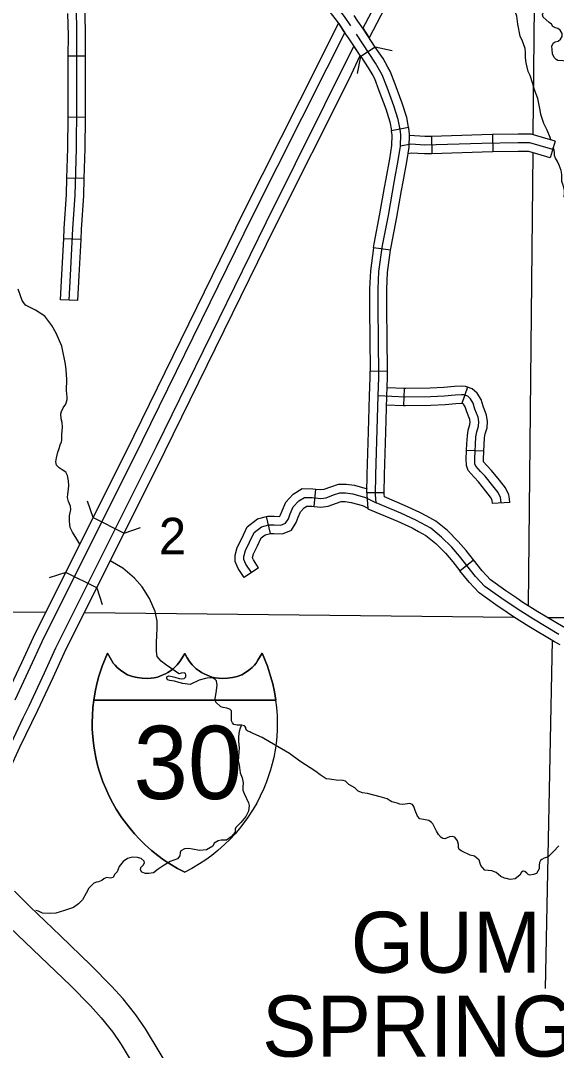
# Model space of a CAD drawing. Extents: x 813775 to 1157140, y 1757555 to 1979907.
# Drawn here: x 966252 to 975531, y 1804482 to 1822306 of the extents above; entities that cross this region are included whole.
import ezdxf

# ---------------------------------------------------------------- set-up
doc = ezdxf.new("R2010")
doc.units = 0
for name, color, linetype in [('Level 10', 7, 'Continuous'), ('Level 19', 7, 'Continuous'), ('Level 23', 7, 'Continuous'), ('Level 31', 7, 'Continuous'), ('Level 32', 7, 'Continuous'), ('Level 35', 7, 'Continuous'), ('Level 37', 7, 'Continuous'), ('Level 38', 7, 'Continuous'), ('Level 39', 7, 'Continuous'), ('Level 4', 7, 'Continuous'), ('Level 5', 7, 'Continuous'), ('Level 6', 7, 'Continuous')]:
    doc.layers.add(name, color=color, linetype=linetype)

msp = doc.modelspace()

# ---------------------------------------------------------------- linework, layer by layer
at = {"layer": 'Level 10'}
for points in [[(966942, 1806463), (966410, 1806971), (966147, 1807238)], [(965792, 1806887), (966060, 1806615), (966596, 1806102)], [(971631, 1799923), (971368, 1800176), (971185, 1800370), (971078, 1800491), (970877, 1800737), (970608, 1801152), (970151, 1801951), (969695, 1802707), (968904, 1804044), (968417, 1804857), (968250, 1805099), (968026, 1805372), (967828, 1805595), (967470, 1805960), (966941, 1806464)], [(966597, 1806101), (967119, 1805604), (967462, 1805254), (967645, 1805048), (967850, 1804798), (967996, 1804586), (968475, 1803788), (969266, 1802450), (969720, 1801698), (970181, 1800892), (970472, 1800442), (970697, 1800168), (970815, 1800033), (971013, 1799824), (971284, 1799563)]]:
    msp.add_lwpolyline(points, dxfattribs=at)
at = {"layer": 'Level 19'}
for p, q in [((972024, 1821867), (970500, 1818807)), ((972134, 1821700), (972024, 1821867)), ((971944, 1821292), (972134, 1821700)), ((970652, 1818730), (971944, 1821292)), ((970500, 1818807), (968598, 1814926)), ((968751, 1814850), (970652, 1818730)), ((968598, 1814926), (966859, 1811443)), ((967011, 1811367), (968751, 1814850))]:
    msp.add_line(p, q, dxfattribs=at)
for points in [[(972227, 1822257), (972339, 1822476), (972780, 1823310), (972987, 1823686), (973351, 1824331)], [(973499, 1824247), (973135, 1823603), (972930, 1823229), (972490, 1822397), (972289, 1822009)], [(971408, 1821562), (971759, 1822261)], [(971759, 1822261), (971867, 1822097)], [(972289, 1822009), (972191, 1822158), (972181, 1822171), (972227, 1822257)], [(971560, 1821486), (971867, 1822097)], [(972182, 1822171), (972289, 1822009)], [(970116, 1819000), (971408, 1821562)], [(970268, 1818924), (971560, 1821486)], [(968213, 1815116), (970116, 1819000)], [(968365, 1815041), (970268, 1818924)], [(966474, 1811634), (968213, 1815116)], [(966626, 1811559), (968365, 1815041)], [(966005, 1810621), (966273, 1811197), (966474, 1811634)], [(966160, 1810550), (966426, 1811123), (966626, 1811559)], [(966859, 1811443), (966661, 1811011), (966395, 1810440)], [(966549, 1810368), (966814, 1810937), (967011, 1811367)], [(966395, 1810440), (966292, 1810231), (966087, 1809802), (965904, 1809413)], [(966058, 1809340), (966241, 1809729), (966446, 1810159), (966549, 1810368)]]:
    msp.add_lwpolyline(points, dxfattribs=at)
at = {"layer": 'Level 23'}
msp.add_line((970670, 1810545), (970668, 1810545), dxfattribs=at)
for points in [[(967519, 1810545), (967541, 1810690), (967570, 1810828), (967608, 1810961), (967662, 1811132), (967755, 1811355), (967826, 1811237), (967857, 1811187), (967888, 1811148), (967927, 1811110), (967984, 1811062), (968042, 1811021), (968106, 1810985), (968188, 1810954), (968269, 1810934), (968355, 1810922), (968446, 1810920), (968512, 1810925), (968566, 1810931), (968625, 1810944), (968706, 1810974), (968759, 1810997), (968803, 1811020), (968846, 1811049), (968897, 1811089), (968965, 1811155), (969012, 1811212), (969051, 1811276), (969094, 1811351)], [(969094, 1811351), (969051, 1811276), (969012, 1811212), (968965, 1811155), (968897, 1811089), (968846, 1811049), (968803, 1811020), (968759, 1810997), (968706, 1810974), (968625, 1810944), (968566, 1810931), (968512, 1810925), (968446, 1810920), (968355, 1810922), (968269, 1810934), (968188, 1810954), (968106, 1810985), (968042, 1811021), (967984, 1811062), (967927, 1811110), (967888, 1811148), (967857, 1811187), (967826, 1811237), (967755, 1811355), (967662, 1811132), (967608, 1810961), (967570, 1810828), (967541, 1810690), (967519, 1810545)], [(969094, 1811351), (969138, 1811276), (969177, 1811212), (969224, 1811155), (969292, 1811089), (969343, 1811049), (969386, 1811020), (969430, 1810997), (969483, 1810974), (969564, 1810944), (969623, 1810931), (969677, 1810925), (969743, 1810920), (969834, 1810922), (969920, 1810934), (970001, 1810954), (970083, 1810985), (970147, 1811021), (970205, 1811062), (970262, 1811110), (970301, 1811148), (970332, 1811187), (970363, 1811237), (970434, 1811355), (970527, 1811132), (970581, 1810961), (970618, 1810828), (970648, 1810690), (970670, 1810545)], [(970670, 1810545), (970648, 1810690), (970618, 1810828), (970581, 1810961), (970527, 1811132), (970434, 1811355), (970363, 1811237), (970332, 1811187), (970301, 1811148), (970262, 1811110), (970205, 1811062), (970147, 1811021), (970083, 1810985), (970001, 1810954), (969920, 1810934), (969834, 1810922), (969743, 1810920), (969677, 1810925), (969623, 1810931), (969564, 1810944), (969483, 1810974), (969430, 1810997), (969386, 1811020), (969343, 1811049), (969292, 1811089), (969224, 1811155), (969177, 1811212), (969138, 1811276), (969094, 1811351)], [(967521, 1810545), (967506, 1810415), (967496, 1810281), (967493, 1810156), (967494, 1810043), (967501, 1809911), (967513, 1809797), (967524, 1809714), (967554, 1809554), (967580, 1809442), (967608, 1809340), (967642, 1809234), (967679, 1809129), (967726, 1809014), (967786, 1808883), (967848, 1808764), (967910, 1808657), (968006, 1808509), (968124, 1808350), (968223, 1808232), (968310, 1808139), (968405, 1808045), (968520, 1807943), (968627, 1807857), (968728, 1807783), (968838, 1807710), (968969, 1807631), (969094, 1807565)], [(969094, 1807565), (968969, 1807631), (968838, 1807710), (968728, 1807783), (968627, 1807857), (968520, 1807943), (968405, 1808045), (968310, 1808139), (968223, 1808232), (968124, 1808350), (968006, 1808509), (967910, 1808657), (967848, 1808764), (967786, 1808883), (967726, 1809014), (967679, 1809129), (967642, 1809234), (967608, 1809340), (967580, 1809442), (967554, 1809554), (967524, 1809714), (967513, 1809797), (967501, 1809911), (967494, 1810043), (967493, 1810156), (967496, 1810281), (967506, 1810415), (967521, 1810545)], [(970670, 1810545), (967519, 1810545)], [(967519, 1810545), (970670, 1810545)], [(967519, 1810545), (970670, 1810545)], [(970668, 1810545), (970683, 1810415), (970693, 1810281), (970696, 1810156), (970695, 1810043), (970688, 1809911), (970676, 1809797), (970664, 1809714), (970635, 1809554), (970609, 1809442), (970581, 1809340), (970547, 1809234), (970510, 1809129), (970463, 1809014), (970403, 1808883), (970341, 1808764), (970279, 1808657), (970183, 1808509), (970065, 1808350), (969966, 1808232), (969879, 1808139), (969784, 1808045), (969669, 1807943), (969562, 1807857), (969461, 1807783), (969351, 1807710), (969220, 1807631), (969094, 1807565)], [(970668, 1810545), (970683, 1810415), (970693, 1810281), (970696, 1810156), (970695, 1810043), (970688, 1809911), (970676, 1809797), (970664, 1809714), (970635, 1809554), (970609, 1809442), (970581, 1809340), (970547, 1809234), (970510, 1809129), (970463, 1809014), (970403, 1808883), (970341, 1808764), (970279, 1808657), (970183, 1808509), (970065, 1808350), (969966, 1808232), (969879, 1808139), (969784, 1808045), (969669, 1807943), (969562, 1807857), (969461, 1807783), (969351, 1807710), (969220, 1807631), (969094, 1807565)]]:
    msp.add_lwpolyline(points, dxfattribs=at)
at = {"layer": 'Level 31'}
for p, q in [((972675, 1820405), (972970, 1820461)), ((972660, 1818331), (972363, 1818371)), ((972304, 1816241), (972604, 1816244)), ((972550, 1814130), (972250, 1814133)), ((972250, 1814133), (972250, 1814133)), ((973860, 1812785), (974095, 1812972))]:
    msp.add_line(p, q, dxfattribs=at)
for points in [[(971969, 1822214), (971862, 1822379), (971680, 1822607), (971433, 1822977), (971177, 1823305), (970999, 1823522), (970717, 1823840), (970626, 1823916), (970516, 1824001), (970390, 1824095), (970292, 1824140), (970117, 1824205), (970033, 1824267), (969945, 1824345), (969890, 1824478), (969864, 1824631), (969864, 1824972), (969874, 1825319), (969871, 1825736), (969874, 1825837), (969884, 1826032), (969893, 1826574), (969910, 1827828), (969914, 1828922)], [(967119, 1817903), (967158, 1818701), (967197, 1819287), (967219, 1820095), (967226, 1820830), (967229, 1822048), (967219, 1822577)], [(971778, 1822232), (971740, 1822292), (971538, 1822549)], [(972395, 1821849), (972191, 1822158), (972093, 1822297), (972030, 1822395)], [(972144, 1821684), (971943, 1821989), (971844, 1822130), (971778, 1822232)], [(972409, 1813960), (972400, 1814105), (972403, 1814446), (972443, 1815809), (972455, 1816129), (972449, 1816817), (972445, 1817301), (972445, 1817662), (972458, 1817961), (972520, 1818416), (972621, 1818932), (972728, 1819540), (972793, 1819887), (972831, 1820131), (972836, 1820334), (972825, 1820420), (972793, 1820592), (972718, 1820829), (972598, 1821151), (972514, 1821369), (972400, 1821569), (972067, 1822074)], [(972610, 1821502), (972528, 1821648), (972395, 1821849), (972144, 1821684)], [(972144, 1821684), (972272, 1821491), (972349, 1821354)], [(972970, 1820461), (972938, 1820628), (972860, 1820877), (972738, 1821205), (972650, 1821433), (972610, 1821502)], [(972349, 1821354), (972378, 1821304), (972458, 1821098), (972576, 1820780), (972647, 1820555), (972675, 1820405)], [(972849, 1819363), (972875, 1819513), (972940, 1819861), (972981, 1820117), (972986, 1820342), (972973, 1820443), (972970, 1820461)], [(972553, 1819415), (972580, 1819566), (972645, 1819913), (972682, 1820144), (972686, 1820326), (972677, 1820396), (972675, 1820405)], [(972363, 1818371), (972372, 1818440), (972473, 1818959), (972553, 1819415)], [(972660, 1818331), (972668, 1818391), (972768, 1818904), (972849, 1819363)], [(972363, 1818371), (972309, 1817974), (972295, 1817666), (972295, 1817300), (972296, 1817297)], [(972595, 1817300), (972595, 1817302), (972595, 1817659), (972608, 1817948), (972660, 1818331)], [(967096, 1817468), (967119, 1817903)], [(972296, 1817298), (972299, 1816816), (972304, 1816241)], [(972604, 1816244), (972599, 1816818), (972595, 1817300)], [(972275, 1815191), (972293, 1815814), (972305, 1816131), (972304, 1816241)], [(972575, 1815183), (972593, 1815804), (972605, 1816127), (972604, 1816244)], [(972250, 1814133), (972253, 1814449), (972275, 1815191)], [(972550, 1814130), (972553, 1814443), (972575, 1815183)], [(972250, 1814133), (972250, 1814101), (972265, 1813858), (972776, 1813641), (973030, 1813524), (973143, 1813463)], [(973285, 1813727), (973164, 1813793), (972898, 1813916), (972553, 1814062), (972550, 1814109), (972550, 1814130)], [(975572, 1811682), (975133, 1811946), (974867, 1812112), (974569, 1812316), (974293, 1812514), (974131, 1812686), (973852, 1813037), (973720, 1813191), (973541, 1813366), (973356, 1813519), (973097, 1813658), (972837, 1813779), (972409, 1813960)], [(974095, 1812972), (973968, 1813133), (973829, 1813293), (973642, 1813478), (973440, 1813644), (973285, 1813727)], [(973143, 1813463), (973272, 1813394), (973441, 1813255), (973610, 1813088), (973736, 1812941), (973860, 1812785)], [(974847, 1812308), (974655, 1812439), (974392, 1812628), (974244, 1812785), (974095, 1812972)], [(974677, 1812060), (974483, 1812193), (974194, 1812401), (974017, 1812588), (973860, 1812785)], [(975731, 1811770), (975645, 1811814), (975211, 1812074), (974949, 1812237), (974847, 1812308)], [(975597, 1811502), (975500, 1811551), (975055, 1811818), (974785, 1811986), (974677, 1812060)]]:
    msp.add_lwpolyline(points, dxfattribs=at)
at = {"layer": 'Level 32'}
for p, q in [((967378, 1821688), (967078, 1821689)), ((967374, 1820631), (967074, 1820634)), ((973366, 1820302), (973376, 1820003)), ((974425, 1820333), (974428, 1820033)), ((975510, 1820218), (975424, 1819930)), ((967355, 1819572), (967055, 1819581)), ((967299, 1818515), (966999, 1818529)), ((967246, 1817460), (966946, 1817475)), ((973991, 1815964), (973894, 1815680)), ((972896, 1815939), (972883, 1815639)), ((974274, 1814854), (973974, 1814863)), ((971337, 1813897), (971364, 1814196)), ((974722, 1813966), (974422, 1813948)), ((970580, 1813429), (970509, 1813721)), ((970374, 1812836), (970125, 1812669))]:
    msp.add_line(p, q, dxfattribs=at)
for points in [[(967078, 1821689), (967079, 1822047), (967072, 1822427)], [(967378, 1821688), (967379, 1822049), (967372, 1822435)], [(967074, 1820634), (967076, 1820831), (967078, 1821689)], [(967374, 1820631), (967376, 1820830), (967378, 1821688)], [(967055, 1819581), (967069, 1820098), (967074, 1820634)], [(967355, 1819572), (967369, 1820093), (967374, 1820631)], [(973366, 1820302), (973254, 1820299), (972986, 1820317)], [(974425, 1820333), (974237, 1820331), (973366, 1820302)], [(975510, 1820218), (975291, 1820283), (975091, 1820338), (974869, 1820338), (974425, 1820333)], [(975467, 1820074), (975249, 1820139), (975071, 1820188), (974870, 1820188), (974241, 1820181), (973251, 1820149), (973008, 1820165), (972831, 1820131)], [(973376, 1820003), (973249, 1819998), (973017, 1820014), (972963, 1820003)], [(974428, 1820033), (974244, 1820031), (973376, 1820003)], [(975424, 1819930), (975208, 1819995), (975051, 1820038), (974871, 1820038), (974428, 1820033)], [(966999, 1818529), (967008, 1818710), (967047, 1819294), (967055, 1819581)], [(967299, 1818515), (967307, 1818693), (967346, 1819280), (967355, 1819572)], [(966946, 1817475), (966969, 1817910), (966999, 1818529)], [(967246, 1817460), (967268, 1817895), (967299, 1818515)], [(973991, 1815964), (973959, 1815975), (973887, 1815980), (973768, 1815974), (973582, 1815955), (973345, 1815944), (972921, 1815938), (972896, 1815939)], [(974274, 1814854), (974277, 1814962), (974287, 1815084), (974298, 1815153), (974330, 1815260), (974337, 1815370), (974321, 1815479), (974262, 1815633), (974225, 1815746), (974160, 1815855), (974074, 1815935), (973991, 1815964)], [(974572, 1813957), (974569, 1814010), (974562, 1814051), (974520, 1814137), (974428, 1814256), (974295, 1814419), (974216, 1814503), (974135, 1814594), (974120, 1814636), (974117, 1814719), (974123, 1814852), (974127, 1814971), (974138, 1815102), (974151, 1815187), (974182, 1815287), (974187, 1815364), (974175, 1815440), (974120, 1815583), (974088, 1815684), (974042, 1815760), (973995, 1815804), (973929, 1815826), (973885, 1815830), (973780, 1815825), (973593, 1815805), (973350, 1815794), (972918, 1815787), (972443, 1815809)], [(972896, 1815939), (972599, 1815952)], [(972883, 1815639), (972589, 1815652)], [(973899, 1815678), (973883, 1815679), (973791, 1815675), (973604, 1815656), (973354, 1815644), (972916, 1815637), (972883, 1815639)], [(973974, 1814863), (973977, 1814979), (973989, 1815120), (974004, 1815220), (974033, 1815315), (974036, 1815357), (974029, 1815402), (973979, 1815533), (973950, 1815621), (973924, 1815665), (973917, 1815672), (973894, 1815680)], [(974422, 1813948), (974420, 1813994), (974418, 1814005), (974392, 1814057), (974310, 1814162), (974182, 1814321), (974105, 1814402), (974003, 1814517), (973971, 1814608), (973967, 1814720), (973974, 1814858), (973974, 1814863)], [(974722, 1813966), (974718, 1814027), (974707, 1814097), (974648, 1814217), (974545, 1814349), (974408, 1814518), (974326, 1814605), (974269, 1814669), (974267, 1814718), (974273, 1814847), (974274, 1814854)], [(970509, 1813721), (970533, 1813726), (970643, 1813726), (970730, 1813724), (970742, 1813729), (970755, 1813750), (970780, 1813822), (970845, 1813971), (970974, 1814109), (971129, 1814205), (971312, 1814200), (971364, 1814196)], [(971364, 1814196), (971448, 1814188), (971508, 1814194), (971623, 1814237), (971756, 1814282), (971890, 1814282), (972037, 1814263), (972251, 1814202)], [(970551, 1813576), (970641, 1813576), (970758, 1813573), (970842, 1813609), (970891, 1813683), (970920, 1813768), (970972, 1813888), (971070, 1813992), (971170, 1814054), (971303, 1814050), (971449, 1814037), (971543, 1814047), (971673, 1814096), (971780, 1814132), (971880, 1814132), (972007, 1814115), (972224, 1814054), (972409, 1813960)], [(970569, 1813426), (970639, 1813426), (970787, 1813422), (970943, 1813489), (971027, 1813617), (971060, 1813714), (971100, 1813805), (971165, 1813875), (971211, 1813903), (971295, 1813901), (971337, 1813897)], [(971337, 1813897), (971450, 1813887), (971578, 1813900), (971723, 1813954), (971804, 1813982), (971871, 1813982), (971977, 1813968), (972170, 1813913), (972265, 1813865)], [(970125, 1812669), (970021, 1812825), (969967, 1812944), (969967, 1813053), (970005, 1813187), (970082, 1813343), (970174, 1813544), (970355, 1813683), (970509, 1813721)], [(970249, 1812753), (970152, 1812899), (970117, 1812977), (970117, 1813032), (970146, 1813133), (970217, 1813279), (970295, 1813447), (970421, 1813545), (970551, 1813576)], [(970374, 1812836), (970284, 1812972), (970267, 1813009), (970267, 1813011), (970286, 1813078), (970353, 1813214), (970416, 1813351), (970488, 1813407), (970580, 1813429)]]:
    msp.add_lwpolyline(points, dxfattribs=at)
at = {"layer": 'Level 35'}
for points in [[(975407, 1822276), (975353, 1822318), (975301, 1822366), (975290, 1822407), (975289, 1822415), (975324, 1822484), (975389, 1822540), (975446, 1822574), (975461, 1822607), (975460, 1822645), (975429, 1822710)], [(975009, 1821575), (974993, 1821660), (974998, 1821752), (974991, 1821826), (974965, 1821887), (974941, 1821951), (974903, 1822035), (974862, 1822246), (974847, 1822381), (974806, 1822492)], [(975737, 1821606), (975686, 1821605), (975645, 1821609), (975558, 1821616), (975524, 1821631), (975490, 1821665), (975465, 1821733), (975459, 1821804), (975449, 1821865), (975472, 1821914), (975510, 1821941), (975561, 1821953), (975604, 1821987), (975630, 1822031), (975631, 1822081), (975593, 1822140), (975557, 1822171), (975516, 1822183), (975468, 1822206), (975448, 1822243), (975407, 1822276)], [(975267, 1820666), (975233, 1820843), (975211, 1820960), (975149, 1821106), (975123, 1821211), (975076, 1821355), (975044, 1821426), (975009, 1821575)], [(975433, 1820240), (975422, 1820282), (975369, 1820408), (975315, 1820526), (975267, 1820666)], [(975494, 1820062), (975477, 1820107)], [(975663, 1819248), (975672, 1819312), (975668, 1819366), (975648, 1819460), (975626, 1819524), (975623, 1819591), (975624, 1819640), (975612, 1819713), (975576, 1819803), (975548, 1819870), (975516, 1819928), (975495, 1819973), (975497, 1820021), (975494, 1820062)], [(966335, 1817380), (966277, 1817459), (966210, 1817659)], [(967029, 1816361), (966964, 1816674), (966868, 1816899), (966794, 1817030), (966673, 1817193), (966508, 1817294), (966428, 1817334), (966335, 1817380)], [(967057, 1815789), (967050, 1815904), (967052, 1816093), (967041, 1816263), (967029, 1816361)], [(966964, 1815043), (966964, 1815145), (966977, 1815268), (966974, 1815348), (966956, 1815413), (966950, 1815501), (966958, 1815542), (966989, 1815601), (967038, 1815665), (967057, 1815749), (967057, 1815789)], [(966970, 1815103), (966970, 1815104)], [(966973, 1814533), (966918, 1814567), (966874, 1814611), (966864, 1814671), (966873, 1814741), (966898, 1814834), (966920, 1814898), (966940, 1814965), (966961, 1815014), (966964, 1815043)], [(967084, 1813981), (967065, 1814052), (967072, 1814108), (967082, 1814194), (967089, 1814261), (967084, 1814338), (967074, 1814371), (967062, 1814432), (967037, 1814489), (966973, 1814533)], [(967278, 1813245), (967224, 1813332), (967149, 1813454), (967109, 1813534), (967107, 1813585), (967101, 1813643), (967097, 1813735), (967121, 1813844), (967116, 1813902), (967084, 1813981)], [(968617, 1811913), (968583, 1812076), (968484, 1812305), (968359, 1812507), (968227, 1812653), (968020, 1812826), (967805, 1812958)], [(968686, 1811217), (968617, 1811302), (968606, 1811387), (968606, 1811536), (968609, 1811671), (968620, 1811783), (968617, 1811913)], [(968929, 1811044), (968856, 1811097), (968761, 1811163), (968686, 1811217)], [(968923, 1810943), (968997, 1810920), (969042, 1810916), (969082, 1810917), (969114, 1810950), (969114, 1810981), (969107, 1811003), (969082, 1811019), (969033, 1811012), (968998, 1810999), (968969, 1811015), (968929, 1811044)], [(969638, 1810669), (969657, 1810805), (969644, 1810876), (969613, 1810906), (969576, 1810932), (969478, 1810924), (969342, 1810890), (969188, 1810815), (969055, 1810834), (969024, 1810844), (968994, 1810847), (968915, 1810871), (968835, 1810882), (968798, 1810898), (968784, 1810924), (968787, 1810948), (968822, 1810967), (968875, 1810953), (968923, 1810943)], [(969902, 1810357), (969882, 1810380), (969857, 1810395), (969823, 1810406), (969761, 1810418), (969719, 1810429), (969631, 1810508), (969619, 1810572), (969638, 1810669)], [(970223, 1809993), (970189, 1810005), (970171, 1810023), (970155, 1810050), (970152, 1810069), (970128, 1810098), (970079, 1810113), (970004, 1810111), (969947, 1810121), (969921, 1810152), (969905, 1810186), (969902, 1810357)], [(970079, 1810113), (970057, 1810057), (970035, 1810000), (970024, 1809913), (970024, 1809828), (970038, 1809717), (970033, 1809649), (970024, 1809559), (970022, 1809496), (970038, 1809426), (970057, 1809287), (970087, 1809197), (970106, 1809115), (970098, 1809039)], [(971439, 1809252), (971363, 1809308), (971087, 1809490), (970906, 1809618), (970662, 1809767), (970433, 1809900), (970239, 1809985), (970223, 1809993)], [(973677, 1808177), (973598, 1808144), (973563, 1808147), (973537, 1808165), (973489, 1808216), (973457, 1808277), (973391, 1808402), (973367, 1808428), (973324, 1808460), (973229, 1808476), (973168, 1808492), (973123, 1808535), (973085, 1808636), (973061, 1808702), (973040, 1808739), (972992, 1808755), (972873, 1808737), (972820, 1808742), (972772, 1808760), (972679, 1808787), (972650, 1808803), (972599, 1808835), (972557, 1808848), (972477, 1808870), (972262, 1808931), (972174, 1808939), (972100, 1808971), (972039, 1809024), (971938, 1809082), (971877, 1809141), (971840, 1809154), (971718, 1809159), (971603, 1809175), (971542, 1809183), (971439, 1809252)], [(970098, 1809039), (970101, 1808989), (970125, 1808929), (970198, 1808768), (970212, 1808719), (970201, 1808624), (970152, 1808529), (970068, 1808425), (969978, 1808338), (969967, 1808311), (969965, 1808257), (969899, 1808178), (969820, 1808121), (969723, 1808118), (969671, 1808107), (969603, 1808066), (969581, 1808015), (969472, 1807955), (969350, 1807941), (969228, 1807966), (969168, 1807976), (969092, 1807968), (969029, 1807938), (969016, 1807906), (969008, 1807851), (968967, 1807797)], [(973891, 1807929), (973849, 1807962), (973836, 1807996), (973836, 1808044), (973820, 1808108), (973770, 1808172), (973733, 1808186), (973677, 1808177)], [(975570, 1808020), (975482, 1807927), (975389, 1807834), (975320, 1807810), (975280, 1807789), (975254, 1807770), (975235, 1807736), (975233, 1807680), (975230, 1807622), (975188, 1807544), (975134, 1807528), (975068, 1807515), (975041, 1807526), (975018, 1807550), (974986, 1807576), (974954, 1807584), (974927, 1807566), (974895, 1807515), (974818, 1807454), (974728, 1807438), (974667, 1807459), (974632, 1807462), (974566, 1807494), (974489, 1807560)], [(968967, 1807797), (968842, 1807749), (968723, 1807676), (968633, 1807619), (968552, 1807556), (968475, 1807542), (968413, 1807542), (968350, 1807567), (968331, 1807605), (968337, 1807646), (968372, 1807687), (968397, 1807728), (968391, 1807760), (968342, 1807806), (968274, 1807823), (968187, 1807828), (968106, 1807806), (968027, 1807752), (967959, 1807665), (967923, 1807572), (967880, 1807529), (967853, 1807474), (967807, 1807464), (967741, 1807472), (967695, 1807453), (967657, 1807420), (967600, 1807398), (967565, 1807395), (967521, 1807376)], [(974223, 1807682), (974192, 1807773), (974152, 1807808), (974110, 1807842), (974038, 1807863), (973891, 1807929)], [(974489, 1807560), (974415, 1807590), (974351, 1807595), (974293, 1807603), (974248, 1807648), (974223, 1807682)], [(967521, 1807376), (967432, 1807290), (967389, 1807206), (967326, 1807089), (967253, 1807021), (967166, 1806953), (967013, 1806904), (966861, 1806858), (966747, 1806852), (966633, 1806858), (966565, 1806890), (966519, 1806906)]]:
    msp.add_lwpolyline(points, dxfattribs=at)
at = {"layer": 'Level 38'}
for points in [[(972395, 1821850), (972689, 1821790)], [(972084, 1821391), (972144, 1821684)]]:
    msp.add_lwpolyline(points, dxfattribs=at)
at = {"layer": 'Level 39'}
for p, q in [((967507, 1813703), (967412, 1813988)), ((967507, 1813703), (968043, 1813435)), ((968043, 1813435), (968328, 1813530)), ((967033, 1812755), (966748, 1812660)), ((967570, 1812487), (967033, 1812755)), ((967570, 1812487), (967665, 1812202))]:
    msp.add_line(p, q, dxfattribs=at)
at = {"layer": 'Level 4'}
for points in [[(963256, 1812112), (964533, 1812091), (964828, 1812086), (966689, 1812066)], [(967356, 1812059), (974794, 1811980)], [(975374, 1811977), (975815, 1811975)]]:
    msp.add_lwpolyline(points, dxfattribs=at)
at = {"layer": 'Level 5'}
for points in [[(975148, 1822561), (975125, 1820328)], [(975122, 1820018), (975041, 1812180)], [(975455, 1811577), (975335, 1805555)]]:
    msp.add_lwpolyline(points, dxfattribs=at)

# ---------------------------------------------------------------- texts
at = {"layer": 'Level 23'}
msp.add_text('30', height=1267.2, dxfattribs=at).set_placement((968207, 1808833))
at = {"layer": 'Level 37'}
msp.add_text('2', height=634, dxfattribs=at).set_placement((968647, 1813066))
at = {"layer": 'Level 6'}
for s, p in [('GUM', (971970, 1805826)), ('SPRINGS', (970434, 1804374))]:
    msp.add_text(s, height=1056, dxfattribs=at).set_placement(p)

doc.saveas('drawing.dxf')
